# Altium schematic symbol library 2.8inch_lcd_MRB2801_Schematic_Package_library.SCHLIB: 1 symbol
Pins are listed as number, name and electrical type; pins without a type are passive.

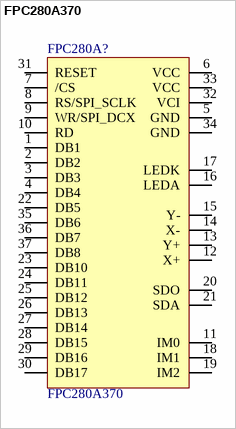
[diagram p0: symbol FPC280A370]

## FPC280A370
designator FPC280A?
footprint TFT2.8' (TFT,LCD,320*240,2.8',TOUCH,8/16bit)
pins: 1 DB1, 2 DB2, 3 DB3, 4 DB4, 5 GND, 6 VCC, 7 /CS, 8 RS/SPI_SCLK, 9 WR/SPI_DCX, 10 RD, 11 IM0, 12 X+, 13 Y+, 14 X-, 15 Y-, 16 LEDA, 17 LEDK, 18 IM1, 19 IM2, 20 SDO, 21 SDA, 22 DB5, 23 DB10, 24 DB11, 25 DB12, 26 DB13, 27 DB14, 28 DB15, 29 DB16, 30 DB17, 31 RESET, 32 VCI, 33 VCC, 34 GND, 35 DB6, 36 DB7, 37 DB8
